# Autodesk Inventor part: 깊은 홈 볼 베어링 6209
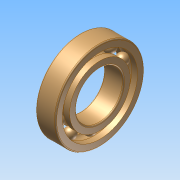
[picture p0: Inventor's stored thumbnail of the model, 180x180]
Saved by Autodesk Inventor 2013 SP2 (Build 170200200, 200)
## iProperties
Created: 2025-06
Part Number: 깊은 홈 볼 베어링 6209
Material: Generic
Document SubType Name: Modeling
Designer: a
Density: 1 g/cm^3
Author: a
변환 표준: STEP AP214IS
전처리기: Build: 200, Release: 2013 SP2 Update 6 - Date: Thu 07/17/2014
전송 단위: 밀리미터
불확실성: 0.01
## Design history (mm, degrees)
node "깊은 홈 볼 베어링 62091"
body "Solid1"
node "Solid1_1"
node "Solid1_2"
node "Solid1_3"
node "Solid1_4"
node "Solid1_5"
node "Solid1_6"
node "Solid1_7"
node "Solid1_8"
node "Solid1_9"
node "Solid1_10"
node "Solid1_11"
node "기준1"
node "기준2"
node "기준3"
node "기준4"
node "기준5"
node "기준6"
node "기준7"
node "기준8"
node "기준9"
node "기준10"
node "기준11"
node "기준12"
